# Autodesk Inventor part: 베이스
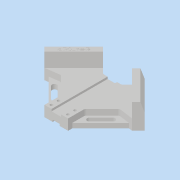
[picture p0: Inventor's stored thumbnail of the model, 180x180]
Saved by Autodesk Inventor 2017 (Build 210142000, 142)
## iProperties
Part Number: 베이스
Material: 일반
Document SubType Name: Modeling
Designer: 222
Density: 1 g/cm^3
Appearance: 기본값
Author: 222
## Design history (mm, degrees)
sketch "스케치1"
  geometry: L1 (0, 149.706)-(-84.853, 64.853); L2 (-84.853, 64.853)-(0, -20); L3 (0, -20)-(0, 149.706); 1 further point
  constraints: 6 end point, 1 vertical, 1 vertical alignment
  dimensions: "d0" = 90 deg angle of L2 L1; "d1" = 45 deg angle of L3 L1; "d2" = 120 distance of L1.start L1.end; "d3" = 20 distance of point (0, 0) L2.end
extrude "돌출1" new body sketch "스케치1" distance "d4" = 18; taper "d5" = 0 deg
sketch "스케치2"
  geometry: L1 (-20, 0)-(-20, 28.284); L2 (-84.853, 64.853)-(0, -20) reference; L3 (-20, 28.284)-(-49.497, 57.782); L4 (-49.497, 57.782)-(-74.246, 54.246); L5 (-20, 7.071)-(-68.059, 55.13); L6 (-74.246, 54.246)-(-20, 0); L7 (0, 149.706)-(-84.853, 64.853) reference; 1 further point
  constraints: 10 end point, 4 point on line, 2 parallel, 1 collinear, 1 vertical
  dimensions: "d7" = 20 distance of point (0, 0) L1.start; "d11" = 15 distance of L4.end L2.start; "d12" = 20 distance between parallel lines of L2 L3; "d13" = 5 distance between parallel lines of L2 L5; "d58" = 30 distance from line of L3.end L7
extrude "돌출2" cut sketch "스케치2" stored distance "d15" = 18; taper "d16" = 0 deg
extrude "돌출3" cut sketch "스케치2" distance "d17" = 10; taper "d18" = 0 deg
sketch "스케치3"
  geometry: L1 (-52.326, 49.296)-(-26.87, 23.841); L2 (-52.326, 43.64)-(-32.527, 23.841); L3 (-26.87, 29.497)-(-46.669, 49.296); L4 (-49.497, 57.782)-(-20, 28.284) reference; L5 (0, 149.706)-(-84.853, 64.853) reference; L6 (-84.853, 64.853)-(-74.246, 54.246) reference; A1 r 4 centre (-49.497, 46.468) between (-46.669, 49.296) and (-52.326, 43.64); A2 r 4 centre (-29.698, 26.669) between (-32.527, 23.841) and (-26.87, 29.497); 2 further points
  constraints: 8 end point, 6 point on circle, 4 tangent, 2 centre point, 2 parallel, 2 point on line, 1 midpoint
  dimensions: "d19" = 28 distance of A2.centre A1.centre; "d20" = 38 distance from line of A1.centre L5; "d21" = 12 distance from line of A1.centre L6; "d22" = 4 radius of A1
extrude "돌출4" cut sketch "스케치3" stored distance "d23" = 10; taper "d24" = 0 deg
sketch "스케치4"
  geometry: L1 (-20, 0)-(0, -20) reference; L2 (-20, 0)-(0, 0); L3 (0, 0)-(0, -20); L4 (0, -20)-(-20, -20); L5 (-20, -20)-(-20, 0); L6 (0, -20)-(0, 149.706) reference; 1 further point
  constraints: 8 end point, 2 parallel, 2 point on line, 1 horizontal, 1 perpendicular
extrude "돌출5" cut sketch "스케치4" stored distance "d25" = 10; taper "d26" = 0 deg
sketch "스케치5"
  geometry: L1 (-35.355, 114.35)-(-16.005, 95); L2 (-16.005, 95)-(0, 95); L3 (-20, 0)-(0, 0) reference; L4 (-84.853, 64.853)-(-74.246, 54.246) reference; L5 (0, 149.706)-(-84.853, 64.853) reference; L6 (0, 0)-(0, 149.706) reference; L7 (0, 95)-(0, 149.706)
  constraints: 6 end point, 1 collinear, 1 horizontal, 1 parallel, 1 point on line
  dimensions: "d27" = 95 distance between parallel lines of L2 L3; "d28" = 50 distance of L5.start L1.start
extrude "돌출6" cut sketch "스케치5" stored distance "d29" = 10; taper "d30" = 0 deg
sketch "스케치6"
  geometry: L1 (-84.853, 64.853)-(-35.355, 114.35); L2 (-35.355, 114.35)-(-24.749, 103.744); L3 (-24.749, 103.744)-(-74.246, 54.246); L4 (-74.246, 54.246)-(-84.853, 64.853); L5 (-35.355, 114.35)-(-84.853, 64.853) reference; 1 further point
  constraints: 8 end point, 3 equal length, 1 perpendicular
  dimensions: "d31" = 15 distance of L3.end L1.start
extrude "돌출7" join sketch "스케치6" distance "d32" = 24; taper "d33" = 0 deg
chamfer "모따기1" distance "d34" = 5; stored, may be unused: second distance "d35" = 15, angle "d36" = 45 deg
sketch "스케치7"
  geometry: L1 (0, 0)-(0, 95) reference; L2 (0, 95)-(-8, 95); L3 (-8, 95)-(-8, 0); L4 (-8, 0)-(0, 0); L5 (0, 0)-(0, 95)
  constraints: 8 end point, 2 parallel, 1 horizontal, 1 perpendicular
  dimensions: "d37" = 8 distance of L1.end L2.end
extrude "돌출8" cut sketch "스케치7" distance "d38" = 3.5; taper "d39" = 0 deg
sketch "스케치8"
  geometry: L1 (0, 0)-(6, 0); L2 (6, 0)-(6, 95); L3 (6, 95)-(0, 95); L4 (0, 95)-(0, 0); 1 further point
  constraints: 8 end point, 2 parallel, 1 coincident, 1 horizontal, 1 perpendicular
  dimensions: "d40" = 6 distance of L1.start L1.end
extrude "돌출9" cut sketch "스케치8" distance "d41" = 3; taper "d42" = 0 deg
sketch "스케치9"
  geometry: L1 (6, 0)-(0, 0) reference; 2 further points
  constraints: 1 vertical alignment
  dimensions: "d43" = 14 horizontal distance of point (14, 6) L1.end; "d44" = 6 distance from line of point (14, 6) L1; "d45" = 12 distance of point (14, 18) point (14, 6)
hole "구멍1" sketch "스케치9" at (14, 6), (14, 18) diameter "d46" = 4.5; stored, may be unused: countersink angle "d50" = 90 deg, drill point angle "d52" = 118 deg; dims "d47" = 6, "d48" = 8, "d49" = 10, "d51" = 8
sketch "스케치10"
  geometry: L1 (-31.82, 110.815)-(-35.355, 114.35) reference; L2 (-74.246, 54.246)-(-24.749, 103.744) reference; 2 further points
  constraints: 1 other
  dimensions: "d53" = 35 distance from line of point (-53.033, 82.53) L1; "d54" = 5 distance from line of L2 point (-53.033, 82.53)
feature "엠보싱1" sketch "스케치10" dims "d0" = 90 deg, "d1" = 45 deg, "d2" = 120, "d3" = 20, "d19" = 28, "d20" = 38, "d21" = 12, "d22" = 4, "d55" = 0.5, "d56" = 0
fillet "모깎기1" dims "d57" = 5
node "솔리드1"
mirror "미러1"
